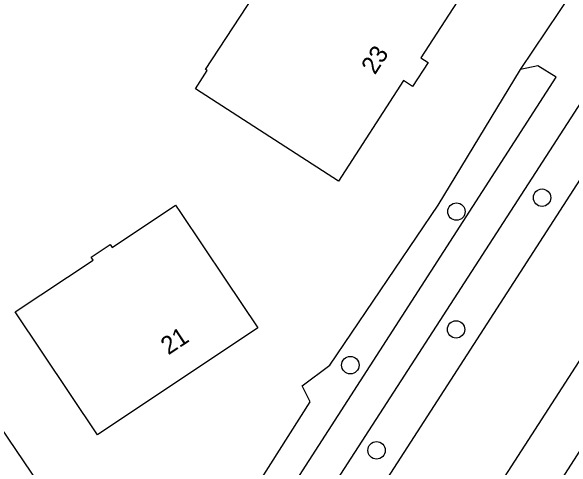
# Model space of a CAD drawing. Extents: x 158797 to 159887, y 384318 to 385255.
# Drawn here: x 158913.69 to 158945.21, y 384708.61 to 384734.28 of the extents above; entities that cross this region are included whole.
import ezdxf

# ---------------------------------------------------------------- set-up
doc = ezdxf.new("R2010")
doc.units = 0
for name, color, linetype in [('IMGEO_Boom', 7, 'Continuous'), ('IMGEO_Groenvoorziening', 7, 'Continuous'), ('IMGEO_Haag', 7, 'Continuous'), ('IMGEO_Pand', 7, 'Continuous'), ('IMGEO_Pand_nummerreeks', 7, 'Continuous'), ('IMGEO_Rijbaan_lokaal_open', 7, 'Continuous'), ('IMGEO_Voetpad_open', 7, 'Continuous')]:
    doc.layers.add(name, color=color, linetype=linetype)

msp = doc.modelspace()

# ---------------------------------------------------------------- linework, layer by layer
at = {"layer": 'IMGEO_Boom'}
for centre in [(158943.536, 384723.796), (158938.724, 384723.017), (158938.701, 384716.392), (158932.755, 384714.384), (158934.228, 384709.595)]:
    msp.add_circle(centre, 0.489, dxfattribs=at)
at = {"layer": 'IMGEO_Groenvoorziening'}
for points in [[(158899.474, 384750.866), (158892.722, 384740.964), (158921.437, 384698.523), (158922.798, 384700.654)], [(158924.704, 384703.639), (158925.321, 384704.179), (158930.5, 384712.328), (158930.039, 384713.226), (158931.6, 384714.377), (158937.688, 384723.377), (158942.331, 384730.999)]]:
    msp.add_lwpolyline(points, dxfattribs=at)
at = {"layer": 'IMGEO_Haag'}
msp.add_lwpolyline([(158966.613, 384739.202), (158965.512, 384740.522), (158941.142, 384702.551), (158952.786, 384686.235), (158953.822, 384686.947)], dxfattribs=at)
at = {"layer": 'IMGEO_Pand'}
for points in [[(158940.106, 384736.899), (158936.719, 384731.662), (158937.125, 384731.4), (158936.259, 384730.054), (158935.738, 384730.375), (158932.09, 384724.725), (158924.046, 384729.914), (158924.708, 384730.939), (158924.607, 384731.005), (158930.08, 384739.364), (158928.014, 384740.701), (158929.552, 384743.078), (158927.869, 384744.166), (158929.188, 384746.205), (158937.122, 384741.073), (158936.099, 384739.491), (158940.106, 384736.899)], [(158927.55, 384716.477), (158918.541, 384710.469), (158913.915, 384717.384), (158918.286, 384720.287), (158918.176, 384720.454), (158919.246, 384721.165), (158919.357, 384720.998), (158922.93, 384723.372), (158923.203, 384722.964), (158925.71, 384719.223), (158927.55, 384716.477)]]:
    msp.add_lwpolyline(points, dxfattribs=at)
at = {"layer": 'IMGEO_Rijbaan_lokaal_open'}
for points in [[(158964.561, 384743.963), (158951.852, 384724.265), (158938.197, 384703.116)], [(158929.826, 384700.232), (158947.905, 384728.262)]]:
    msp.add_lwpolyline(points, dxfattribs=at)
at = {"layer": 'IMGEO_Voetpad_open'}
for points in [[(158942.331, 384730.999), (158945.25, 384735.359)], [(158924.704, 384703.639), (158926.304, 384702.596), (158944.331, 384730.562), (158943.308, 384731.203), (158942.331, 384730.999)], [(158947.905, 384728.262), (158945.951, 384729.508), (158927.819, 384701.473), (158929.826, 384700.232)]]:
    msp.add_lwpolyline(points, dxfattribs=at)

# ---------------------------------------------------------------- texts
at = {"layer": 'IMGEO_Pand_nummerreeks'}
for s, rotation, p in [('23', 57.1525, (158934.139, 384730.664)), ('21', 33.5008, (158922.521, 384714.93))]:
    msp.add_text(s, height=1, rotation=rotation, dxfattribs=at).set_placement(p)

doc.saveas('drawing.dxf')
